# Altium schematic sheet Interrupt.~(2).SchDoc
size A; SheetNumber: 1; SheetTotal: 1
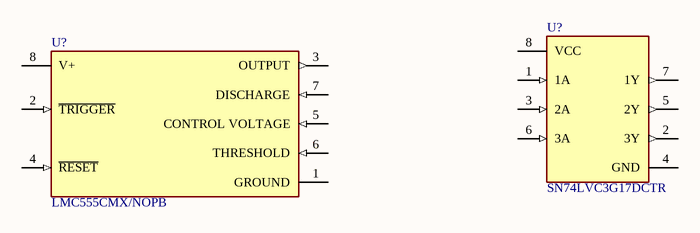
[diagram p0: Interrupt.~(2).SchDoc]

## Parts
(Parts that share a designator on the sheet are numbered #1, #2 ... from top to bottom, then left to right.)
U?#1  SN74LVC3G17DCTR  [FP-DCT0008A-MFG]
U?#2  LMC555CMX/NOPB  [FP-D0008A-MFG]

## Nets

Not connected (* = marked no-connect by the designer): U?#1 1(1A) 2(3Y) 3(2A) 4(GND) 5(2Y) 6(3A) 7(1Y) 8(VCC); U?#2 1(GROUND) 2(~{TRIGGER}) 3(OUTPUT) 4(~{RESET}) 5(CONTROL_VOLTAGE) 6(THRESHOLD) 7(DISCHARGE) 8(V+)

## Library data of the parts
U?#1 = CMP-0859-00525-5: IC BUFFER NON-INVERT 5.5V SM8; Manufacturer: Texas Instruments; Logic Function Desc: Non-Inverting; Propagation Delay: 5.1ns; Number Of Inputs: 3; Description: Buffer, Non-Inverting 3 Element 1 Bit per Element Push-Pull Output SM8 (SSOP); Standoff Height: 0mm; Nominal Supply Current: 10uA; Min Supply Voltage: 1.65V
U?#2 = CMP-04858-000001-1: IC OSC SINGLE TIMER 3MHZ 8-SOIC; Manufacturer: Texas Instruments; Description: 555 Type, Timer/Oscillator (Single) IC 3MHz 8-SOIC; Number Of Timers/Counters: 1; Max Supply Voltage: 15V; Standoff Height: 0.11mm; Propagation Delay: 100ns; Nominal Supply Current: 50-150uA; Min Supply Voltage: 1.5V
